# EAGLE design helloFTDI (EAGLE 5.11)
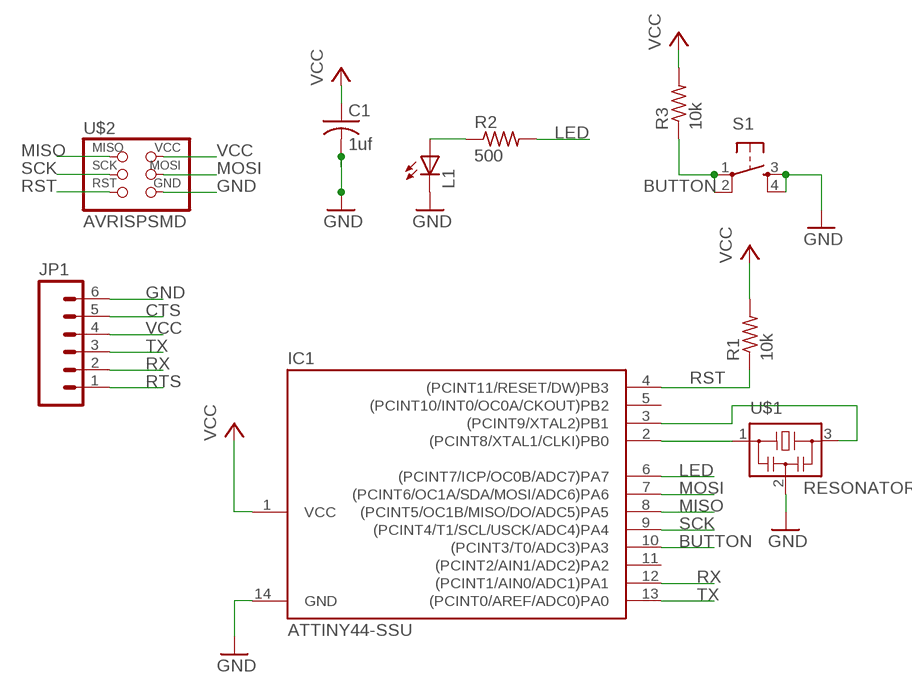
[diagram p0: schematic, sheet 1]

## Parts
C1  1uf  C-USC1206  [C1206]
IC1  ATTINY44-SSU  [SOIC14]
JP1  M06SMD  [1X06-SMD]
L1  LED1206  [1206]
R1  10k  R-US_R1206  [R1206]
R2  500  RESISTOR1206  [1206]
R3  10k  RESISTOR1206  [1206]
S1  6MM_SWITCH6MM_SWITCH  [6MM_SWITCH]
U$1  RESONATOR  [EFOBM]
U$2  AVRISPSMD  [2X03SMD]

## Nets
BUTTON: IC1.10((PCINT3/T0/ADC3)PA3) R3.1 S1.1(P) S1.2(P1)
CTS: JP1.5
GND: C1.2 IC1.14(GND) JP1.6 L1.2(C) S1.3(S) S1.4(S1) U$1.2 U$2.6(GND)
LED: IC1.6((PCINT7/ICP/OC0B/ADC7)PA7) R2.2
MISO: IC1.8((PCINT5/OC1B/MISO/DO/ADC5)PA5) U$2.1(MISO)
MOSI: IC1.7((PCINT6/OC1A/SDA/MOSI/ADC6)PA6) U$2.4(MOSI)
N$1: IC1.2((PCINT8/XTAL1/CLKI)PB0) U$1.1
N$2: IC1.3((PCINT9/XTAL2)PB1) U$1.3
N$3: L1.1(A) R2.1
RST: IC1.4((PCINT11/RESET/DW)PB3) R1.1 U$2.5(RST)
RTS: JP1.1
RX: IC1.12((PCINT1/AIN0/ADC1)PA1) JP1.2
SCK: IC1.9((PCINT4/T1/SCL/USCK/ADC4)PA4) U$2.3(SCK)
TX: IC1.13((PCINT0/AREF/ADC0)PA0) JP1.3
VCC: C1.1 IC1.1(VCC) JP1.4 R1.2 R3.2 U$2.2(VCC)
Unconnected: IC1.5((PCINT10/INT0/OC0A/CKOUT)PB2) IC1.11((PCINT2/AIN1/ADC2)PA2)

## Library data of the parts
C1 = rcl:C-US: CAPACITOR, American symbol
IC1 = fab:ATTINY44
JP1 = SparkFun:M06: Header 6 Standard 6-pin 0.1" header. Use with straight break away headers (SKU : PRT-00116), right angle break away headers (PRT-00553), swiss pins (PRT-00743), machine pins (PRT-00117), and female headers (PRT-00115). Molex polarized connector foot print use with SKU : PRT-08094 with associated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
L1 = ng:LED
R1 = resistor:R-US_: RESISTOR, American symbol
R2 R3 = ng:RESISTOR
S1 = fab:6MM_SWITCH: OMRON SWITCH
U$1 = fab:RESONATOR
U$2 = fab:AVRISP

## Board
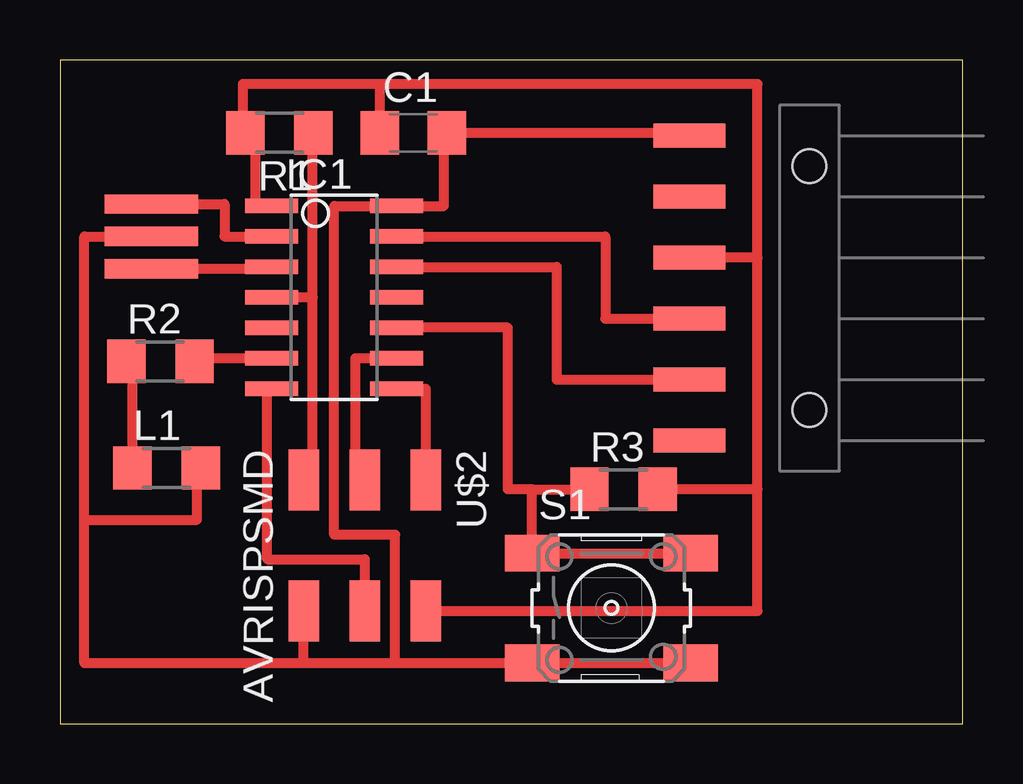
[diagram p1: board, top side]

Size 37.64 x 27.68 mm. Coordinates in mm from the lower left corner, seen from the top.
Outline: 0,0 37.64,0 37.64,27.68 0,27.68 0,0
Copper layers 1: Top 0.035mm
Design rules "ERP-1sided-10mil-16mill": minimum track width 10mil, minimum drill 24mil, track to track 16mil, track to pad 16mil, pad to pad 16mil, via to via 16mil, smd to smd 0mil, copper to edge 16mil, drill to drill 36mil, minimum pad ring 10mil, minimum via ring 8mil, stop-mask expansion 4mil, vias tented up to drill 0mil, thermal gap 10mil

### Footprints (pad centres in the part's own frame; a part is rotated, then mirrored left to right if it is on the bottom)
C1206 = smd 1.6 x 1.8: 1 -1.4,0; 2 1.4,0
SOIC14 = smd 0.61 x 2.21: 1 -3.81,-2.603; 2 -2.54,-2.603; 3 -1.27,-2.603; 4 0,-2.603; 5 1.27,-2.603; 6 2.54,-2.603; 7 3.81,-2.603; 8 3.81,2.603; 9 2.54,2.603; 10 1.27,2.603; 11 0,2.603; 12 -1.27,2.603; 13 -2.54,2.603; 14 -3.81,2.603
1X06-SMD = smd 1 x 3: 1 -6.35,5; 2 -3.81,5; 3 -1.27,5; 4 1.27,5; 5 3.81,5; 6 6.35,5 | hole 1.4: -5.08,0; 5.08,0
1206 = smd 1.6 x 1.803: 1 -1.422,0; 2 1.422,0
R1206 = smd 1.6 x 1.803: 1 -1.422,0; 2 1.422,0
6MM_SWITCH = smd 2.286 x 1.524: 1 -3.302,2.286; 2 3.302,2.286; 3 -3.302,-2.286; 4 3.302,-2.286
EFOBM = smd 0.8 x 3.9: 1 -1.35,0; 2 0,0; 3 1.35,0
2X03SMD = smd 2.54 x 1.27: 1 -2.54,2.54; 2 2.92,2.54; 3 -2.54,0; 4 2.92,0; 5 -2.54,-2.54; 6 2.92,-2.54

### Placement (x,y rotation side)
C1  14.73,24.64 0 top
IC1  11.43,17.78 270 top
JP1  31.24,18.16 90 top
L1  4.45,10.67 0 top
R1  9.14,24.64 180 top
R2  4.19,15.11 0 top
R3  23.5,9.78 0 top
S1  22.99,4.83 0 top
U$1  3.81,20.32 270 top
U$2  12.7,7.62 270 top

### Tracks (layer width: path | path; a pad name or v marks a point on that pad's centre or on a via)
BUTTON
  Top 0.406: S1.2 S1.1 19.68,9.78 | IC1.10 18.67,16.51 18.67,9.78 19.68,9.78 | 19.68,9.78 R3.1 22.61,9.78
GND
  Top 0.406: 13.97,2.54 13.97,7.87 11.43,7.87 11.43,21.59 IC1.14 16,21.59 16,24.64 C1.2 | 10.16,2.54 13.97,2.54 | C1.2 16.13,24.51 | U$1.2 1.02,20.32 1.02,8.51 | U$2.6 10.16,2.54 | 1.02,8.51 1.02,2.54 10.16,2.54 | L1.2 5.71,10.67 5.71,8.51 1.02,8.51 | 13.97,2.54 S1.3 S1.4 | C1.2 26.24,24.64 JP1.6
LED
  Top 0.406: IC1.6 5.61,15.24 R2.2
MISO
  Top 0.406: IC1.8 15.24,13.97 U$2.1
MOSI
  Top 0.406: IC1.7 8.64,13.97 8.64,6.86 12.7,6.86 U$2.4
N$1
  Top 0.406: U$1.1 6.86,21.67 6.86,20.32 IC1.2
N$2
  Top 0.406: U$1.3 8.83,18.97 IC1.3
N$3
  Top 0.406: R2.1 3.02,15.11 L1.1
RST
  Top 0.406: R1.1 10.54,24.64 10.54,17.78 | 10.54,17.78 IC1.4 | U$2.5 10.54,10.16 10.54,17.78
RX
  Top 0.406: IC1.12 20.7,19.05 20.7,14.35 JP1.2
SCK
  Top 0.406: U$2.3 12.32,10.16 12.32,15.24 IC1.9
TX
  Top 0.406: JP1.3 22.73,16.89 22.73,20.32 IC1.13
VCC
  Top 0.406: 13.33,26.67 7.62,26.67 7.62,24.64 R1.2 8.13,24.64 8.13,21.59 IC1.1 | U$2.2 29.08,4.7 29.08,9.78 | 29.08,9.78 R3.2 | 29.08,9.78 29.08,19.43 | 29.08,19.43 JP1.4 | 29.08,19.43 29.08,26.67 13.33,26.67 | 13.33,26.67 C1.1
